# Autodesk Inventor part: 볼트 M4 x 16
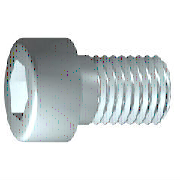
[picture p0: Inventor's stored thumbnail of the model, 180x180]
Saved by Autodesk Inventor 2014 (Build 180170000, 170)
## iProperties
Created: 2012-02
Part Number: 볼트 M4 x 16
Material: 스테인리스강
Description: 6각 소켓 머리 캡 나사
Document SubType Name: Modeling
Standard: ISO 4762
Designer: mduedu
Standard Revision: Fourth edition 2004-03-01
Standards Organization: ISO
Language: ko-KR
Size Designation: M4 x 16
Categories: <MemberInstance><Categories><Category DisplayName="조임쇠" InternalName="e4da775c-781d-43d5-af7c-5136215cf5a6" Mnemonic="FSTN"><Category DisplayName="볼트" InternalN
Density: 7.75 g/cm^3
Appearance: 반광택
IsCustomPart: 0
Author: mduedu
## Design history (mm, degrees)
sketch "스케치1"
  geometry: L1 (-1, 0)-(16, 0); L2 (16, 0)-(16, 2); L3 (16, 2)-(1.75, 2); L4 (1.75, 2)-(1.32, 2); L5 (1.32, 2)-(0, 2); L6 (0, 2)-(0, 3.5); L7 (0, 3.5)-(-4, 3.5); L8 (-4, 3.5)-(-4, 1.732); L9 (-4, 1.732)-(-2, 1.732); L10 (-2, 1.732)-(-1, 0); L11 (-8, 0)-(20, 0) reference; L12 (0, -0.7)-(0, 4.2) reference; L13 (1.75, 2)-(0, 2)
  constraints: 22 end point, 6 parallel, 2 collinear, 2 perpendicular, 1 horizontal, 1 point on line
  dimensions: "d1" = 14.25 distance from line of L3.end L2 (= GEL); "d2" = 0.42952 distance of L4.end L3.end (computed from GAL); "d3" = 4 distance between parallel lines of L8 L6 (= KOH); "d4" = 2 distance of L8.end L9.end (= INTI); "d5" = 60 deg angle of L10 L1; "d6" = 4 diameter of L3 L1 (= GD); "d7" = 4 diameter of L5 L1 (= BDM); "d8" = 3.4641 diameter of L9 L1 (= 1.1547 x SW); "d9" = 7 diameter of L7 L1 (= KOD); "d26" = 16 distance between parallel lines of L12 L2 (= NLG)
revolve "본체" sketch "스케치1" stored, may be unused: angle "d10" = 90 deg
sketch "스케치2"
  geometry: L1 (0, -4.9)-(0, 4.9) reference; L2 (-4.9, 0)-(4.9, 0) reference; L3 (1.732, 0)-(0.866, -1.5); L4 (0.866, -1.5)-(-0.866, -1.5); L5 (-0.866, -1.5)-(-1.732, 0); L6 (-1.732, 0)-(-0.866, 1.5); L7 (-0.866, 1.5)-(0.866, 1.5); L8 (0.866, 1.5)-(1.732, 0); 2 further points
  constraints: 12 end point, 1 coincident, 1 horizontal alignment, 1 point on line, 12 other
extrude "슬롯" join sketch "스케치2" stored distance "d11" = 10; taper "d12" = 0 deg
workplane "Work Plane1"
fillet "Fillet2" dims "d30" = 0.1 (= R)
body "Solid1"
fillet "모깎기1" dims "d17" = 0.4 (= RR)
feature "스레드" dims "d13" = 14.25 (= GEL), "d14" = 0
chamfer "모따기1" distance "d15" = 0.42941 (= -0.5 x SPD + 0.5 x GD); stored, may be unused: second distance "d16" = 0.42941 (= GUL), angle "d27" = 45 deg
other parameters: "GD" = 4 [user parameter; used in 2 equation terms], "NLG" = 16 [user parameter; used in 1 equation term], "GEL" = 14.25 [user parameter; used in 2 equation terms], "KOD" = 7 [user parameter; used in 1 equation term], "KOH" = 4 [user parameter; used in 1 equation term], "INTI" = 2 [user parameter; used in 1 equation term], "GAL" = 0.42941 (= 0.61345 x PTC) [user parameter; used in 1 equation term], "GUL" = 0.42941 (= 0.61345 x PTC) [user parameter; used in 1 equation term], "BDM" = 4 (= NND) [user parameter; used in 1 equation term], "SW" = 3 [user parameter; used in 2 equation terms], "RR" = 0.4 [user parameter; used in 1 equation term], "SPD" = 3.14117 (= NND - 1.2269 x PTC) [user parameter; used in 1 equation term], "d19" = 0, "d28" = 0, "d29" = 0, "R" = 0.1 [user parameter; used in 1 equation term], "TOA" = 30 deg [user parameter], "GD1" = 3.14117 (= THREADDIA - 1.2269 x PTC) [user parameter], "THREADDIA" = 4 [user parameter; used in 1 equation term], "FAWI" = 45 deg [user parameter], "TPU" = 14.28571 (computed from PTC) [user parameter], "PTC" = 0.7 [user parameter; used in 5 equation terms], "NND" = 4 [user parameter; used in 2 equation terms], "E0" = 3.465 (= 1.155 x SW) [user parameter]
